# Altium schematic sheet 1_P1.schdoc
size 307 x 218 mm; Symbol: Drawing-Symbol_A4; Device: Drawing-Symbol_A4; @Project Name: New Project_2026-05-26_10-53-35; @Page Count: 1; @Update Date: 2026-05-27; @Create Date: 2026-05-26; @Schematic Name: Pvc_esp-32; @Page No: 1; @Page Name: P1; Company: EasyEDA.com; Version: V1.0; Page Size: A4; @Create Time: 10:53:44; @Update Time: 21:48:54; Width: 1170; Height: 825; Region Start: 1; X Region Count: 6; Y Region Count: 4; Blade Width: 10; Title Block Position: 3; @Board Name: Board1
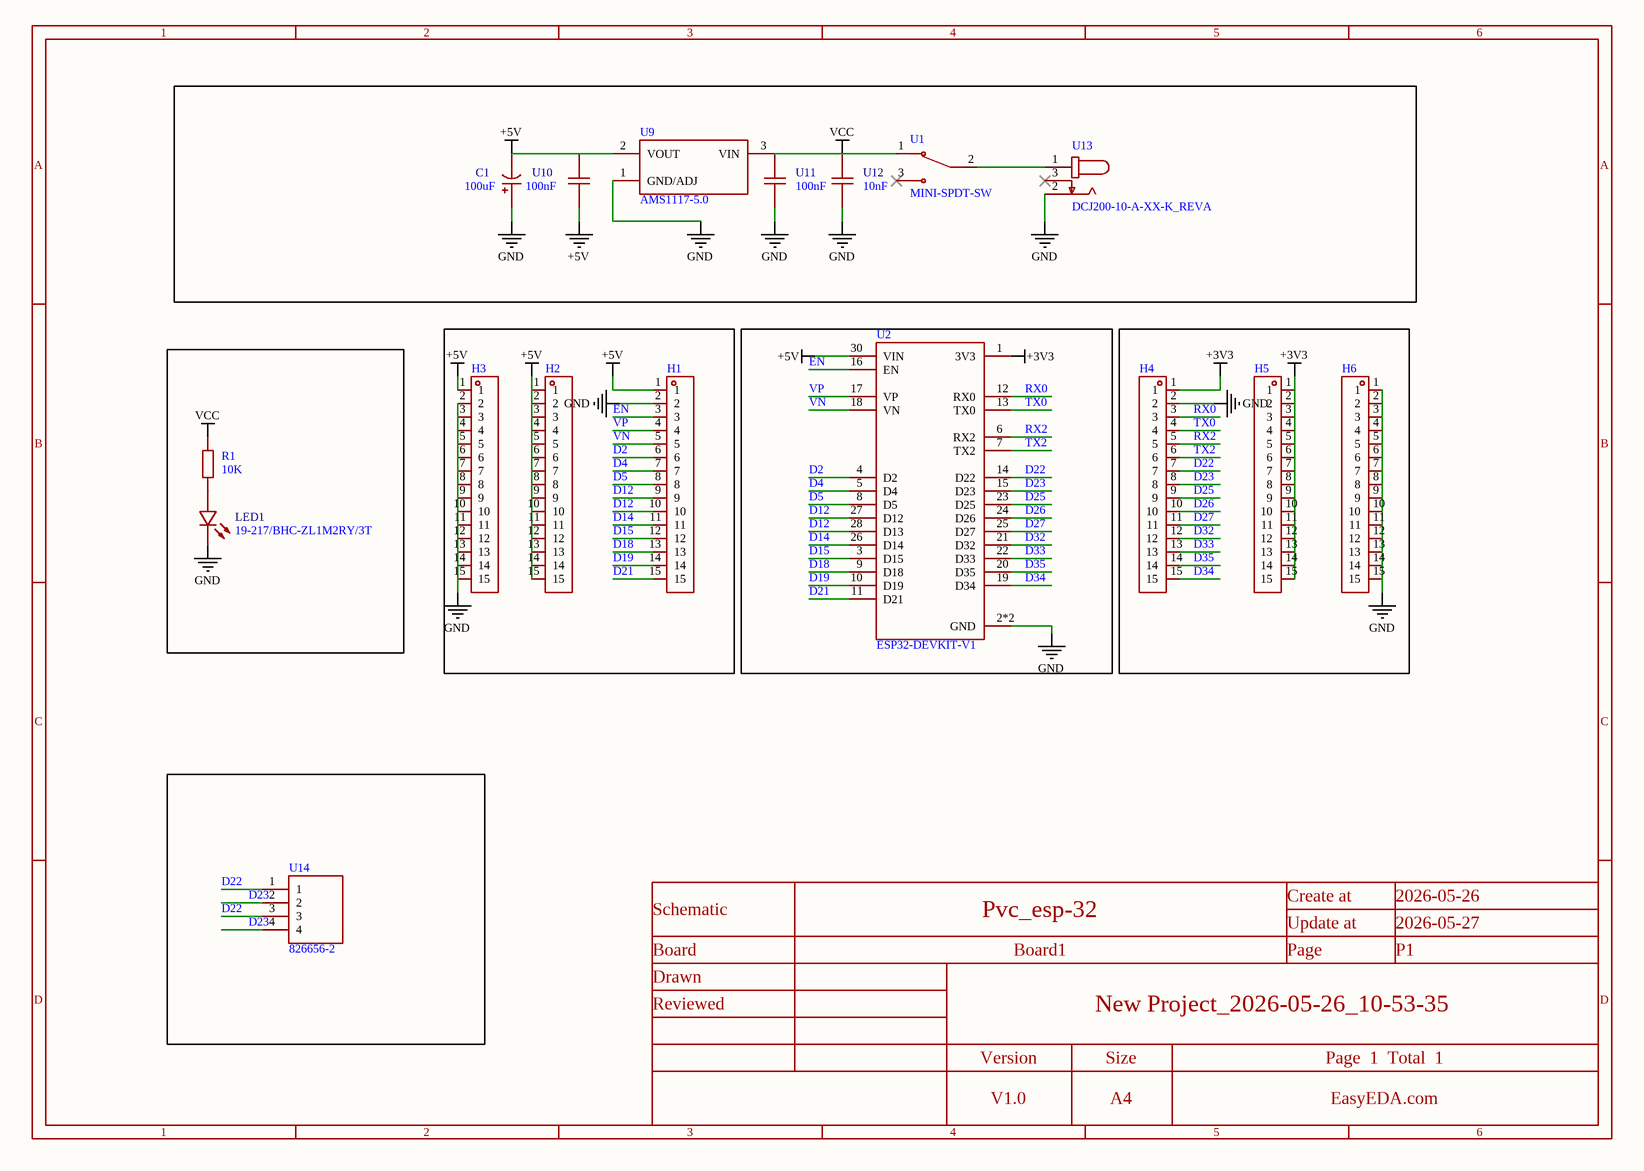
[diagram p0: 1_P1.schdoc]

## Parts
C1  100uF  [CAP-TH_BD8.0-P3.50-D0.6-FD_1]
H1  (no value)  [HDR-TH_15P-P2.54-V-M]
H2  (no value)  [HDR-TH_15P-P2.54-V-M]
H3  (no value)  [HDR-TH_15P-P2.54-V-M]
H4  (no value)  [HDR-TH_15P-P2.54-V-M]
H5  (no value)  [HDR-TH_15P-P2.54-V-M]
H6  (no value)  [HDR-TH_15P-P2.54-V-M]
LED1  19-217/BHC-ZL1M2RY/3T  [LED0603-FD_BLUE]
R1  10K  [R0603]
U1  MINI-SPDT-SW  [SW_MINI-SPDT-SW]
U2  ESP32-DEVKIT-V1  [MODULE_ESP32_DEVKIT_V1]
U9  AMS1117-5.0  [SOT229P700X180-4N]
U10  100nF  [CAP-TH_L5.0-W2.5-P5.00-D1.0]
U11  100nF  [CAP-TH_L5.0-W2.5-P5.00-D1.0]
U12  10nF  [C1206]
U13  DCJ200-10-A-XX-K_REVA  [GCT_DCJ200-10-A-XX-K_REVA]
U14  826656-2  [TE_826656-2]

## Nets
+3V3: H4.1 H5.1 H5.2 H5.3 H5.4 H5.5 H5.6 H5.7 H5.8 H5.9 H5.10 H5.11 H5.12 H5.13 H5.14 H5.15 U2.1(3V3)
+5V: C1.2 H1.1 H2.1 H2.2 H2.3 H2.4 H2.5 H2.6 H2.7 H2.8 H2.9 H2.10 H2.11 H2.12 H2.13 H2.14 H2.15 H3.1 U2.30(VIN) U9.2(VOUT) U10.1 U10.2
GND: C1.1 H1.2 H3.2 H3.3 H3.4 H3.5 H3.6 H3.7 H3.8 H3.9 H3.10 H3.11 H3.12 H3.13 H3.14 H3.15 H4.2 H6.1 H6.2 H6.3 H6.4 H6.5 H6.6 H6.7 H6.8 H6.9 H6.10 H6.11 H6.12 H6.13 H6.14 H6.15 LED1.1(C) U2.2*2(GND) U9.1(GND/ADJ) U11.2 U12.1 U13.2
VCC: R1.2 U1.1 U9.3(VIN) U11.1 U12.2
D2: H1.6 U2.4(D2)
D4: H1.7 U2.5(D4)
D5: H1.8 U2.8(D5)
D12: H1.9 H1.10 U2.27(D12) U2.28(D13)
D14: H1.11 U2.26(D14)
D15: H1.12 U2.3(D15)
D18: H1.13 U2.9(D18)
D19: H1.14 U2.10(D19)
D21: H1.15 U2.11(D21)
D22: H4.7 U2.14(D22) U14.1 U14.3
D23: H4.8 U2.15(D23) U14.2 U14.4
D25: H4.9 U2.23(D25)
D26: H4.10 U2.24(D26)
D27: H4.11 U2.25(D27)
D32: H4.12 U2.21(D32)
D33: H4.13 U2.22(D33)
D34: H4.15 U2.19(D34)
D35: H4.14 U2.20(D35)
EN: H1.3 U2.16(EN)
RX0: H4.3 U2.12(RX0)
RX2: H4.5 U2.6(RX2)
TX0: H4.4 U2.13(TX0)
TX2: H4.6 U2.7(TX2)
VN: H1.5 U2.18(VN)
VP: H1.4 U2.17(VP)
NetLED1_2: LED1.2(A) R1.1
NetU1_2: U1.2 U13.1

Not connected (* = marked no-connect by the designer): U1 3*; U13 3*

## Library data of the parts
C1 = 100uF: Symbol: 100UF_C9900016884; Add into BOM: yes
H1-H6 = HDR-M_2.54_1x15P: Symbol: HDR_2.54-1x15P; Convert to PCB: yes
LED1 = 19-217/BHC-ZL1M2RY/3T: Manufacturer: EVERLIGHT(亿光); Add into BOM: yes; Illumination Color: Blue; Voltage - Forward(Vf): 2.8V; Power(Watts): 110mW; Forward Current: 5mA; Wavelength - Dominant: 465nm~475nm; Peak Wavelength: 468nm; Diode Configuration: Discrete Diode; Lens Color: Water Clear; Luminous Intensity: 24.5mcd~28.5mcd; Viewing Angle: 120°
R1 = Res_0603: Symbol: Res; Convert to PCB: yes
U1 = MINI-SPDT-SW: Add into BOM: yes
U2 = ESP32-DEVKIT-V1: Add into BOM: yes
U9 = AMS1117-5.0: Add into BOM: yes
U10 U11 = 100nF: Symbol: 100NF_C9900015256; Add into BOM: yes
U12 = 10nF: Add into BOM: yes
U13 = DCJ200-10-A-XX-K_REVA: Add into BOM: yes
U14 = 826656-2: Add into BOM: yes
